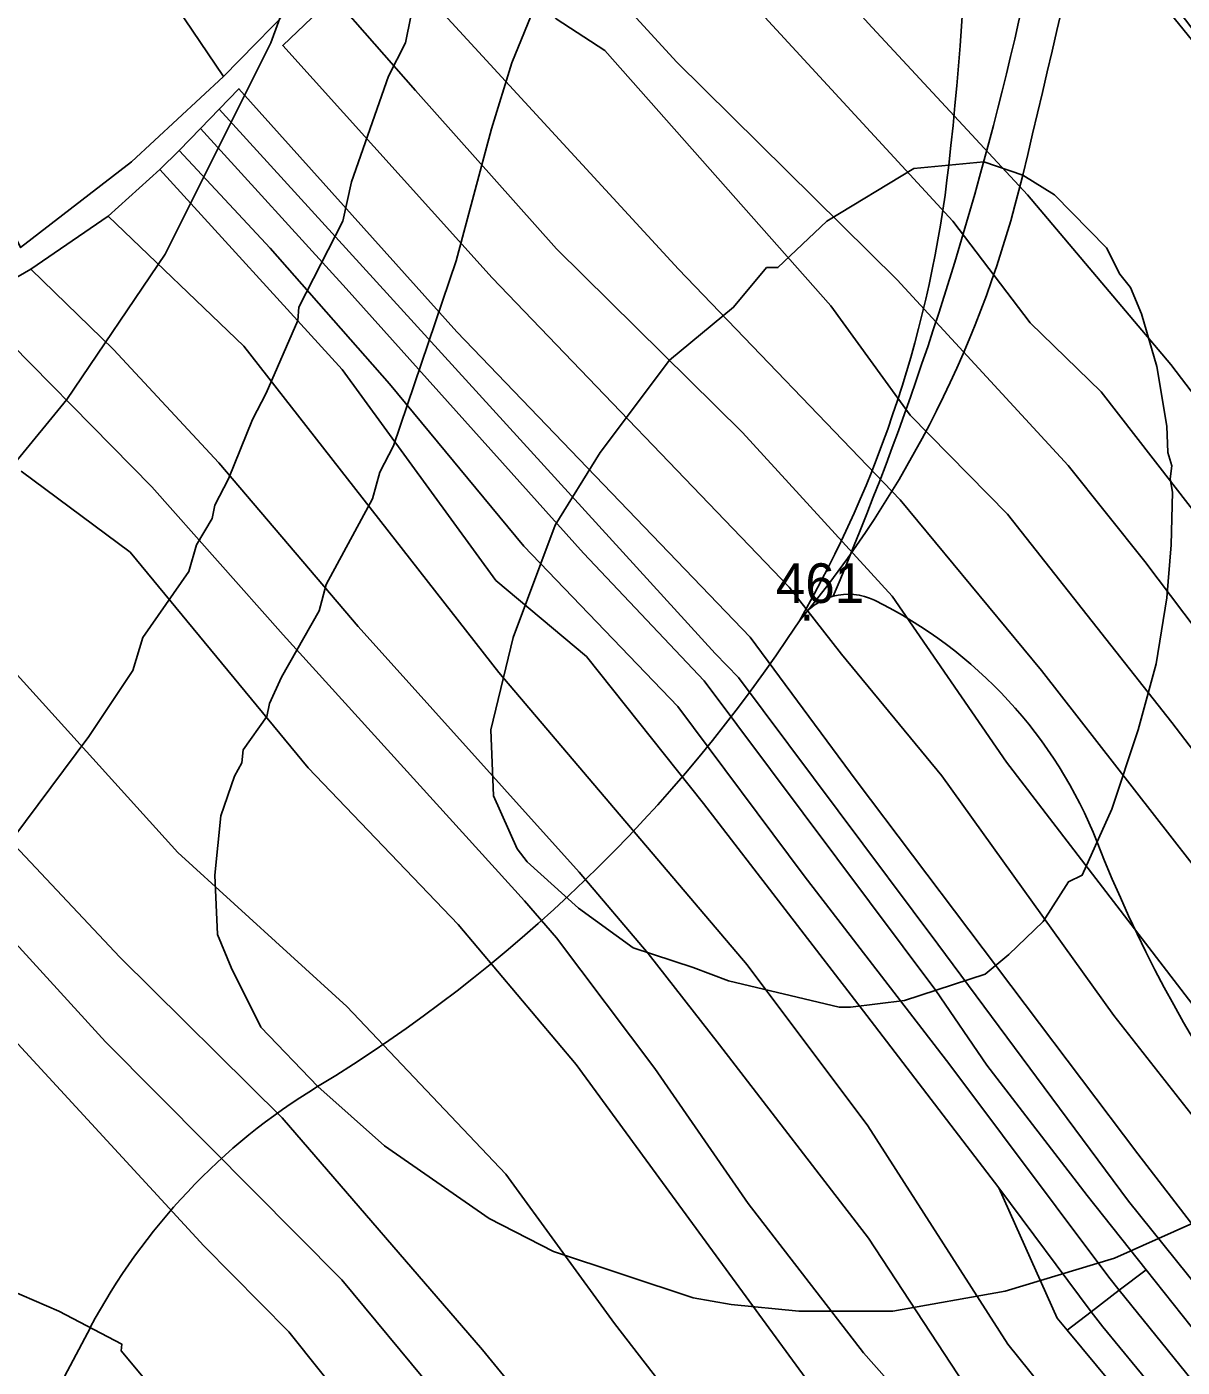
# Model space of a CAD drawing. Extents: x -510989 to -501240, y -1184665 to -1176089.
# Drawn here: x -504241.4 to -504066.3, y -1183034.5 to -1182831.5 of the extents above; entities that cross this region are included whole.
import ezdxf

# ---------------------------------------------------------------- set-up
doc = ezdxf.new("R2010")
doc.units = 0
for name, color, linetype in [('lesni_pozemek', 7, 'Continuous'), ('NAVRH_rozvodnice', 7, 'Continuous'), ('ostatni_plocha_x_neplodna_puda', 7, 'Continuous'), ('ostatni_plocha_x_ostatni_komunikace', 7, 'Continuous'), ('STAV_povodi', 7, 'Continuous'), ('STAV_zaplavove_uzemi', 7, 'Continuous'), ('trvaly_travni_porost', 7, 'Continuous'), ('vrstevnice_01', 7, 'Continuous'), ('vrstevnice_02', 7, 'Continuous'), ('vrstevnice_03', 7, 'Continuous'), ('vrstevnice_05', 7, 'Continuous')]:
    doc.layers.add(name, color=color, linetype=linetype)

msp = doc.modelspace()

# ---------------------------------------------------------------- linework, layer by layer
at = {"layer": 'lesni_pozemek'}
for points in [[(-504123.07, -1182761.98), (-504057.27, -1182842.9), (-504018.48, -1182886.2), (-504018.34, -1182886.36), (-503968.52, -1182943.98), (-503967.63, -1182943.24), (-503966.23, -1182941.71), (-503905.67, -1183023.85), (-503884.5, -1183085.61), (-503880.12, -1183097.81)], [(-503869.63, -1183121.24), (-503886.21, -1183126.14), (-503935.62, -1183062.05), (-503957.32, -1183032.04), (-503997.91, -1182971.84), (-504000.89, -1182967.41), (-504022.97, -1182939.87), (-504031.75, -1182929.1), (-504047.02, -1182910.28), (-504068.07, -1182882.7), (-504089.79, -1182857.01), (-504113.93, -1182830.98)]]:
    msp.add_lwpolyline(points, dxfattribs=at)
for points in [[(-504306.5, -1182923.87), (-504269.17, -1182953.65), (-504246.32, -1182981.7), (-504214.57, -1183016.11), (-504201.67, -1183029.13), (-504177.71, -1183059.2), (-504159.93, -1183078.78), (-504147.85, -1183089.06), (-504131.06, -1183106.62), (-504107.39, -1183130.12), (-504115.19, -1183136.27), (-504124, -1183140.86), (-504129.85, -1183142.24), (-504158.74, -1183113.53), (-504195.78, -1183080.68), (-504225.98, -1183057.01), (-504245.87, -1183037.45), (-504268.75, -1183008.78), (-504270.41, -1183005.75), (-504311.34, -1182950.79), (-504314.92, -1182944.41), (-504312.11, -1182935.85)], [(-504080.12, -1183026.1), (-504078.35, -1183028.41), (-504050.03, -1183062.83), (-504021.15, -1183097.11), (-503993.28, -1183128.08), (-503974.94, -1183163.7), (-503998, -1183130.98), (-504024.54, -1183099.82), (-504055.63, -1183062.75), (-504083.76, -1183028.88)]]:
    msp.add_lwpolyline(points, close=True, dxfattribs=at)
at = {"layer": 'NAVRH_rozvodnice'}
for centre, radius, start, end in [((-506590.51, -1182251.31), 2571.63, 346.44617, 348.739), ((-504606.98, -1182795.32), 508.5, 353.5433, 4.4346), ((-504279.41, -1182832.39), 178.84, 330.1224, 353.5433), ((-504252.65, -1182814.91), 166.8, 320.2893, 346.4462), ((-504116.89, -1182926.36), 8.9, 63.6753, 146.7717), ((-504143.65, -1182980.44), 69.25, 21.558, 63.6753), ((-504316.65, -1182795.5), 229.9, 301.2704, 326.7717), ((-503881.87, -1182877.02), 212.22, 201.558, 227.7054), ((-504148.25, -1183072.79), 94.52, 121.2704, 152.0595), ((-502224.69, -1184093), 2271.88, 152.05953, 156.58006)]:
    msp.add_arc(centre, radius, start, end, dxfattribs=at)
at = {"layer": 'ostatni_plocha_x_neplodna_puda'}
for points in [[(-504071.82, -1183019.74), (-504058.19, -1183036.9), (-504041.02, -1183056.24), (-504023.29, -1183079.53), (-504009.88, -1183094.83), (-503979.33, -1183132.93), (-503972.15, -1183148.99), (-503963, -1183166.75), (-503967.29, -1183167.67), (-503983.91, -1183136.12), (-503990.13, -1183125.9), (-504048.32, -1183056.9), (-504075.88, -1183022.85)], [(-504075.88, -1183022.85), (-504048.32, -1183056.9), (-503990.13, -1183125.9), (-503983.91, -1183136.12), (-503967.29, -1183167.67), (-503969.75, -1183167.67), (-503974.94, -1183163.7), (-503993.28, -1183128.08), (-504021.15, -1183097.11), (-504050.03, -1183062.83), (-504078.35, -1183028.41), (-504080.12, -1183026.1)]]:
    msp.add_lwpolyline(points, close=True, dxfattribs=at)
at = {"layer": 'ostatni_plocha_x_ostatni_komunikace'}
msp.add_lwpolyline([(-504120.45, -1182755.66), (-504119.24, -1182758.24), (-504112.9, -1182771.84), (-504089.67, -1182802.29), (-504082.97, -1182807.91), (-504057.34, -1182841.66), (-504028.33, -1182873.74), (-504005.84, -1182900.48), (-503993.33, -1182913.41), (-503981.65, -1182927.85), (-503967.63, -1182943.24), (-503968.52, -1182943.98), (-504018.34, -1182886.36), (-504018.48, -1182886.2), (-504057.27, -1182842.9), (-504123.07, -1182761.98)], close=True, dxfattribs=at)
at = {"layer": 'STAV_povodi'}
for centre, radius, start, end in [((-504590.46, -1182717.39), 512.06, 336.9635, 356.2363), ((-504116.89, -1182926.36), 8.9, 63.6753, 146.7717), ((-504143.65, -1182980.44), 69.25, 21.558, 63.6753), ((-504316.65, -1182795.5), 229.9, 301.2704, 326.7717), ((-503881.87, -1182877.02), 212.22, 201.558, 227.7054), ((-504148.25, -1183072.79), 94.52, 121.2704, 152.0595), ((-502224.69, -1184093), 2271.88, 152.05953, 156.58006)]:
    msp.add_arc(centre, radius, start, end, dxfattribs=at)
at = {"layer": 'STAV_zaplavove_uzemi'}
msp.add_spline([(-502250.32, -1184002.61), (-502355.07, -1183875.41), (-502442.37, -1183790.61), (-502477.29, -1183700.82), (-502532.16, -1183578.61), (-502567.08, -1183448.91), (-502626.05, -1183402.34), (-502705.41, -1183380.59), (-502814.2, -1183349.87), (-502882.03, -1183297.39), (-502931.95, -1183237.24), (-503042.02, -1183107.97), (-503139.64, -1183018.94), (-503222.14, -1182957.59), (-503308.56, -1182839.96), (-503316.24, -1182784.92), (-503330.32, -1182756.77), (-503348.24, -1182719.65), (-503334.16, -1182651.82), (-503323.92, -1182595.5), (-503313.68, -1182526.39), (-503294.1, -1182480.5), (-503251.86, -1182396.03), (-503229.34, -1182314.37), (-503216.1, -1182227.15), (-503242.43, -1182174.5), (-503271.86, -1182129.59), (-503287.34, -1182081.58), (-503343.88, -1182028.1), (-503361.79, -1182008.91), (-503396.35, -1181952.59), (-503442.43, -1181933.39), (-503497.46, -1181888.6), (-503525.62, -1181860.44), (-503528.18, -1181837.4), (-503548.66, -1181767.01), (-503558.9, -1181729.89), (-503576.82, -1181682.53), (-503578.1, -1181621.1), (-503567.86, -1181572.46), (-503552.5, -1181536.63), (-503538.04, -1181458.36), (-503518.33, -1181411.9), (-503509.88, -1181341.51), (-503497.21, -1181207.63), (-503499.77, -1181097.56), (-503498.02, -1181031.35), (-503510.82, -1180970.85), (-503549.22, -1180952.23), (-503571.32, -1180940.6), (-503605.07, -1180937.11), (-503651.61, -1180939.44), (-503671.39, -1180917.33), (-503679.53, -1180892.89), (-503713.27, -1180871.95), (-503727.24, -1180859.15), (-503734.22, -1180833.55), (-503728.4, -1180799.81), (-503741.2, -1180770.72), (-503722.82, -1180725.17), (-503721.54, -1180703.41), (-503731.78, -1180697.01), (-503767.61, -1180699.57), (-503790.65, -1180697.01), (-503817.53, -1180697.01), (-503861.04, -1180686.77), (-503889.2, -1180675.25), (-503900.72, -1180668.85), (-503953.2, -1180679.09), (-503997.99, -1180697.01), (-504063.27, -1180722.61), (-504109.34, -1180749.49), (-504142.62, -1180776.36), (-504177.18, -1180796.84), (-504211.73, -1180817.32), (-504414.98, -1180961.5), (-504472.7, -1180998.11), (-504544.51, -1181068.5), (-504600.82, -1181143.12), (-504621.94, -1181196.62), (-504641.65, -1181267.01), (-504660.25, -1181350.62), (-504634.7, -1181398.32), (-504617.66, -1181447.72), (-504600.62, -1181492.01), (-504587, -1181548.23), (-504592.11, -1181628.29), (-504569.96, -1181682.81), (-504568.26, -1181664.07), (-504554.63, -1181621.48), (-504547.82, -1181597.63)], degree=3, dxfattribs=at)
at = {"layer": 'trvaly_travni_porost'}
for points in [[(-504235.93, -1182738.25), (-504214.21, -1182772.59), (-504198.46, -1182799.13), (-504187.04, -1182813.97), (-504211.58, -1182839.08), (-504237.33, -1182800.97), (-504264.25, -1182747.48)], [(-504264.25, -1182747.48), (-504237.33, -1182800.97), (-504211.58, -1182839.08), (-504225.53, -1182851.98), (-504242.32, -1182864.99), (-504270.73, -1182806.86), (-504293.81, -1182752.72)], [(-504163.77, -1182796.35), (-504152.42, -1182786.67), (-504138.84, -1182803.26), (-504113.93, -1182830.98), (-504089.79, -1182857.01), (-504068.07, -1182882.7), (-504047.02, -1182910.28), (-504031.75, -1182929.1), (-504022.97, -1182939.87), (-504000.89, -1182967.41), (-504006.62, -1182971.66), (-504010.43, -1182974.49), (-504017.32, -1182966.46), (-504023.18, -1182959.19), (-504028.9, -1182951.41), (-504049.39, -1182924.3), (-504062.53, -1182907.58), (-504078.64, -1182886.84), (-504089.37, -1182876.38), (-504101.08, -1182860.99), (-504139.67, -1182819.08)], [(-504172.88, -1182804.13), (-504163.77, -1182796.35), (-504139.67, -1182819.08), (-504101.08, -1182860.99), (-504089.37, -1182876.38), (-504078.64, -1182886.84), (-504062.53, -1182907.58), (-504049.39, -1182924.3), (-504028.9, -1182951.41), (-504023.18, -1182959.19), (-504017.32, -1182966.46), (-504010.43, -1182974.49), (-504019.83, -1182981.13), (-504044.66, -1182948.73), (-504072, -1182912.53), (-504083.62, -1182897.98), (-504109.55, -1182869.88), (-504142.94, -1182836.87)], [(-504180.5, -1182811.16), (-504172.88, -1182804.13), (-504142.94, -1182836.87), (-504109.55, -1182869.88), (-504083.62, -1182897.98), (-504072, -1182912.53), (-504044.66, -1182948.73), (-504019.83, -1182981.13), (-504029.18, -1182987.53), (-504067.9, -1182936.88), (-504092.79, -1182905.32), (-504107.58, -1182890.35), (-504119.57, -1182873.82), (-504153.82, -1182835.14), (-504161.16, -1182830.35)], [(-504185.12, -1182815.82), (-504180.5, -1182811.16), (-504161.16, -1182830.35), (-504153.82, -1182835.14), (-504119.57, -1182873.82), (-504107.58, -1182890.35), (-504092.79, -1182905.32), (-504067.9, -1182936.88), (-504029.18, -1182987.53), (-504037.4, -1182993.19), (-504059.47, -1182965.15), (-504087.66, -1182929.02), (-504109.07, -1182903.19), (-504142.66, -1182868.27), (-504183.42, -1182823.91), (-504188.1, -1182819.35)], [(-504209.24, -1182840.94), (-504176.21, -1182877.74), (-504131.79, -1182923.95), (-504115.74, -1182945.67), (-504073.09, -1183002.21), (-504056.78, -1183023.32), (-504038.08, -1183045.23), (-504019.05, -1183069.7), (-503977.23, -1183119.54), (-503970.17, -1183129.82), (-503958.75, -1183139.83), (-503949.4, -1183164.1), (-503955.63, -1183165.33), (-503966.58, -1183142), (-503980.53, -1183122.85), (-504010.06, -1183088.12), (-504046.12, -1183043.57), (-504053.07, -1183035.96), (-504074.5, -1183009.36), (-504103.38, -1182970.47), (-504133.57, -1182930.09), (-504137.12, -1182926.46), (-504212.21, -1182844)], [(-504215.08, -1182846.97), (-504193.01, -1182871.15), (-504157.04, -1182911.25), (-504138.75, -1182930.57), (-504103.65, -1182977.48), (-504095.93, -1182988.79), (-504080.74, -1183008.51), (-504071.82, -1183019.74), (-504075.88, -1183022.85), (-504077.47, -1183020.89), (-504101.54, -1182988.7), (-504123.63, -1182960.08), (-504142.76, -1182934.48), (-504166.08, -1182910.21), (-504186.45, -1182885.59), (-504204.49, -1182865.09), (-504218.3, -1182850.3)], [(-504221.23, -1182853.17), (-504218.3, -1182850.3), (-504204.49, -1182865.09), (-504186.45, -1182885.59), (-504166.08, -1182910.21), (-504142.76, -1182934.48), (-504123.63, -1182960.08), (-504101.54, -1182988.7), (-504077.47, -1183020.89), (-504075.88, -1183022.85), (-504080.12, -1183026.1), (-504094.11, -1183007.34), (-504114.11, -1182981.25), (-504138.85, -1182949.16), (-504156.61, -1182926.89), (-504170.31, -1182915.4), (-504193.6, -1182883.44)], [(-504229.03, -1182860.23), (-504221.23, -1182853.17), (-504193.6, -1182883.44), (-504170.31, -1182915.4), (-504156.61, -1182926.89), (-504138.85, -1182949.16), (-504114.11, -1182981.25), (-504094.11, -1183007.34), (-504085.27, -1183027.06), (-504083.76, -1183028.88), (-504055.63, -1183062.75), (-504063.17, -1183066.74), (-504076.32, -1183051.46), (-504092.74, -1183031), (-504113.96, -1182997.97), (-504132.23, -1182973.6), (-504169.87, -1182929.32), (-504208.49, -1182879.92)], [(-504229.03, -1182860.23), (-504208.49, -1182879.92), (-504169.87, -1182929.32), (-504132.23, -1182973.6), (-504113.96, -1182997.97), (-504092.74, -1183031), (-504076.32, -1183051.46), (-504063.17, -1183066.74), (-504072.56, -1183071.72), (-504085.95, -1183055.47), (-504097.19, -1183040.35), (-504113.88, -1183014.98), (-504136.44, -1182985.68), (-504147.26, -1182971.85), (-504157.72, -1182959.55), (-504191.17, -1182922.34), (-504212.29, -1182897.57), (-504228.23, -1182880.43), (-504240.76, -1182868.24)], [(-504285.73, -1182887.74), (-504284.8, -1182886.95), (-504253.85, -1182917.58), (-504218.49, -1182956.59), (-504192.91, -1182979.89), (-504168.79, -1183005.29), (-504152.33, -1183027.9), (-504104.16, -1183090.19), (-504094.88, -1183100.11), (-504076.58, -1183122.48), (-504068.48, -1183132.84), (-504080.16, -1183132.75), (-504092.81, -1183127.66), (-504110.54, -1183108.39), (-504116.17, -1183100.46), (-504172.35, -1183031.85), (-504202.69, -1182996.73), (-504227.29, -1182972.4), (-504251.24, -1182947.01), (-504295.79, -1182905.36), (-504289.8, -1182894.88)], [(-504295.79, -1182905.36), (-504251.24, -1182947.01), (-504227.29, -1182972.4), (-504202.69, -1182996.73), (-504172.35, -1183031.85), (-504116.17, -1183100.46), (-504110.54, -1183108.39), (-504092.81, -1183127.66), (-504100.87, -1183128.23), (-504128.92, -1183098.19), (-504151.68, -1183071.83), (-504193.64, -1183021.29), (-504213.86, -1183000.95), (-504229.46, -1182985.23), (-504263.01, -1182948.5), (-504301.06, -1182913.71)], [(-504306.5, -1182923.87), (-504301.06, -1182913.71), (-504263.01, -1182948.5), (-504229.46, -1182985.23), (-504213.86, -1183000.95), (-504193.64, -1183021.29), (-504151.68, -1183071.83), (-504128.92, -1183098.19), (-504100.87, -1183128.23), (-504107.39, -1183130.12), (-504131.06, -1183106.62), (-504147.85, -1183089.06), (-504159.93, -1183078.78), (-504177.71, -1183059.2), (-504201.67, -1183029.13), (-504214.57, -1183016.11), (-504246.32, -1182981.7), (-504269.17, -1182953.65)], [(-504094.11, -1183007.34), (-504080.12, -1183026.1), (-504083.76, -1183028.88), (-504085.27, -1183027.06)]]:
    msp.add_lwpolyline(points, close=True, dxfattribs=at)
for points in [[(-504242.32, -1182864.99), (-504225.53, -1182851.98), (-504211.58, -1182839.08), (-504187.04, -1182813.97)], [(-504183.42, -1182823.91), (-504142.66, -1182868.27), (-504109.07, -1182903.19), (-504087.66, -1182929.02), (-504059.47, -1182965.15), (-504037.4, -1182993.19), (-504045.86, -1182999.02), (-504028.96, -1183021.79), (-504023.98, -1183027.58), (-504013.41, -1183039.77), (-503966.42, -1183100.15), (-503961.54, -1183107.2), (-503950.2, -1183127.17), (-503963.89, -1183111.68), (-503967.95, -1183106.11), (-503979.54, -1183089.27), (-504014.39, -1183042.85), (-504029.78, -1183025.1), (-504092.96, -1182942.9), (-504110.29, -1182917.76), (-504132.95, -1182892.99), (-504161.14, -1182865.18), (-504182.48, -1182841.19), (-504194.92, -1182827.03)], [(-504194.92, -1182827.03), (-504202.6, -1182834.38), (-504170.88, -1182869.58), (-504125.89, -1182916.41), (-504117.96, -1182926.52), (-504102.78, -1182944.98), (-504076.68, -1182981.26), (-504051.16, -1183013.74)], [(-504051.16, -1183013.74), (-504076.68, -1182981.26), (-504102.78, -1182944.98), (-504117.96, -1182926.52), (-504125.89, -1182916.41), (-504170.88, -1182869.58), (-504202.6, -1182834.38), (-504194.92, -1182827.03), (-504182.48, -1182841.19), (-504161.14, -1182865.18), (-504132.95, -1182892.99), (-504110.29, -1182917.76), (-504092.96, -1182942.9), (-504029.78, -1183025.1)], [(-504056.78, -1183023.32), (-504073.09, -1183002.21), (-504115.74, -1182945.67), (-504131.79, -1182923.95), (-504176.21, -1182877.74), (-504209.24, -1182840.94), (-504212.21, -1182844), (-504215.08, -1182846.97), (-504218.3, -1182850.3), (-504221.23, -1182853.17), (-504229.03, -1182860.23), (-504240.76, -1182868.24), (-504249.79, -1182873.44)], [(-504058.19, -1183036.9), (-504071.82, -1183019.74), (-504080.74, -1183008.51), (-504095.93, -1182988.79), (-504103.65, -1182977.48), (-504138.75, -1182930.57), (-504157.04, -1182911.25), (-504193.01, -1182871.15), (-504215.08, -1182846.97), (-504212.21, -1182844), (-504137.12, -1182926.46), (-504133.57, -1182930.09), (-504103.38, -1182970.47), (-504074.5, -1183009.36), (-504053.07, -1183035.96)], [(-504109.11, -1183038.55), (-504114.65, -1183032.32), (-504132.09, -1183009.71), (-504146.23, -1182989.25), (-504161.13, -1182969.51), (-504165.99, -1182963.88), (-504202.53, -1182923.59), (-504222.45, -1182901.21), (-504249.79, -1182873.44), (-504240.76, -1182868.24), (-504228.23, -1182880.43), (-504212.29, -1182897.57), (-504191.17, -1182922.34), (-504157.72, -1182959.55), (-504147.26, -1182971.85), (-504136.44, -1182985.68), (-504113.88, -1183014.98), (-504097.19, -1183040.35)], [(-504249.79, -1182873.44), (-504222.45, -1182901.21), (-504202.53, -1182923.59), (-504165.99, -1182963.88), (-504161.13, -1182969.51), (-504146.23, -1182989.25), (-504132.09, -1183009.71), (-504114.65, -1183032.32), (-504109.11, -1183038.55), (-504099.22, -1183052.53), (-504080.48, -1183077.05), (-504064.88, -1183095.68)], [(-504242.25, -1182898.82), (-504225.74, -1182911.11), (-504198.74, -1182943.74), (-504176.03, -1182967.46), (-504158.14, -1182988.69), (-504110.81, -1183053.38), (-504100.23, -1183067.74), (-504080.47, -1183088.07), (-504068.23, -1183103.83), (-504054.29, -1183118.52), (-504026.53, -1183145.25), (-504047.07, -1183133.76), (-504058.34, -1183131.22), (-504068.48, -1183132.84), (-504076.58, -1183122.48), (-504094.88, -1183100.11), (-504104.16, -1183090.19), (-504152.33, -1183027.9), (-504168.79, -1183005.29), (-504192.91, -1182979.89), (-504218.49, -1182956.59), (-504253.85, -1182917.58)], [(-504054.29, -1183118.52), (-504068.23, -1183103.83), (-504080.47, -1183088.07), (-504100.23, -1183067.74), (-504110.81, -1183053.38), (-504158.14, -1182988.69), (-504176.03, -1182967.46), (-504198.74, -1182943.74), (-504225.74, -1182911.11), (-504242.25, -1182898.82)]]:
    msp.add_lwpolyline(points, dxfattribs=at)
at = {"layer": 'vrstevnice_01'}
for points in [[(-504273.91, -1182935), (-504235.31, -1182888), (-504220.41, -1182866), (-504204.41, -1182834), (-504192.41, -1182801)], [(-504068.19, -1182900), (-504067.81, -1182902), (-504068, -1182910), (-504068.69, -1182918), (-504070.31, -1182928), (-504073, -1182938), (-504077, -1182950), (-504081.5, -1182960), (-504083.59, -1182961), (-504087.41, -1182967), (-504092.59, -1182972), (-504096.19, -1182975), (-504108.41, -1182979), (-504116.59, -1182980), (-504118.31, -1182980), (-504135.09, -1182976), (-504140.41, -1182974), (-504149.5, -1182971), (-504157.81, -1182965), (-504165.59, -1182958), (-504167.09, -1182956), (-504170.69, -1182948), (-504171.09, -1182938), (-504167.69, -1182924), (-504161.31, -1182907), (-504154.5, -1182896), (-504144, -1182882), (-504134.31, -1182874), (-504129.31, -1182868), (-504127.59, -1182868), (-504120.19, -1182861), (-504107, -1182853), (-504096.41, -1182852), (-504090.5, -1182854), (-504085.69, -1182857), (-504077.81, -1182865), (-504075.81, -1182869), (-504074.19, -1182871), (-504072.5, -1182875), (-504070.19, -1182883), (-504068.69, -1182892), (-504068.5, -1182896), (-504067.91, -1182898), (-504068.19, -1182900)]]:
    msp.add_lwpolyline(points, dxfattribs=at)
at = {"layer": 'vrstevnice_02'}
for points in [[(-504162.59, -1182824), (-504167.91, -1182837), (-504171, -1182847), (-504176.31, -1182867), (-504185.81, -1182895), (-504187.91, -1182899), (-504189, -1182903), (-504196, -1182916), (-504197.09, -1182920), (-504202.81, -1182930), (-504204.59, -1182934), (-504205, -1182936), (-504208.59, -1182941), (-504208.81, -1182943), (-504209.91, -1182945), (-504212, -1182951), (-504212.91, -1182960), (-504212.5, -1182969), (-504210.41, -1182974), (-504205.91, -1182983), (-504197.31, -1182992), (-504187.19, -1183001), (-504171.31, -1183012), (-504161.59, -1183017), (-504140.41, -1183024), (-504134.69, -1183025), (-504124.41, -1183026), (-504110.19, -1183026), (-504093.19, -1183023), (-504076.59, -1183018), (-504060.91, -1183011)], [(-504248.59, -1183167), (-504240.91, -1183157), (-504237.59, -1183154), (-504220.41, -1183125), (-504215.59, -1183111), (-504213, -1183101), (-504212.69, -1183097), (-504211.59, -1183093), (-504210.09, -1183077), (-504210.81, -1183073), (-504210.69, -1183069), (-504211.41, -1183065), (-504216.41, -1183047), (-504220.41, -1183040), (-504227.09, -1183032), (-504227, -1183031), (-504236.5, -1183026), (-504245.91, -1183022)]]:
    msp.add_lwpolyline(points, dxfattribs=at)
at = {"layer": 'vrstevnice_03'}
msp.add_lwpolyline([(-504183.19, -1182830), (-504184, -1182834), (-504186.59, -1182839), (-504192.19, -1182855), (-504193.5, -1182861), (-504200.19, -1182874), (-504200.31, -1182876), (-504205.09, -1182887), (-504207.19, -1182891), (-504210.81, -1182900), (-504212.91, -1182904), (-504213.31, -1182906), (-504215.69, -1182910), (-504216.81, -1182914), (-504223.81, -1182924), (-504225.31, -1182929), (-504232, -1182939), (-504245.41, -1182957)], dxfattribs=at)

# ---------------------------------------------------------------- texts
at = {"layer": 'vrstevnice_05'}
for s, p in [('461', (-504127.91, -1182918.79)), ('.', (-504124.34, -1182921.48))]:
    msp.add_text(s, height=6, dxfattribs=at).set_placement(p)

doc.saveas('drawing.dxf')
